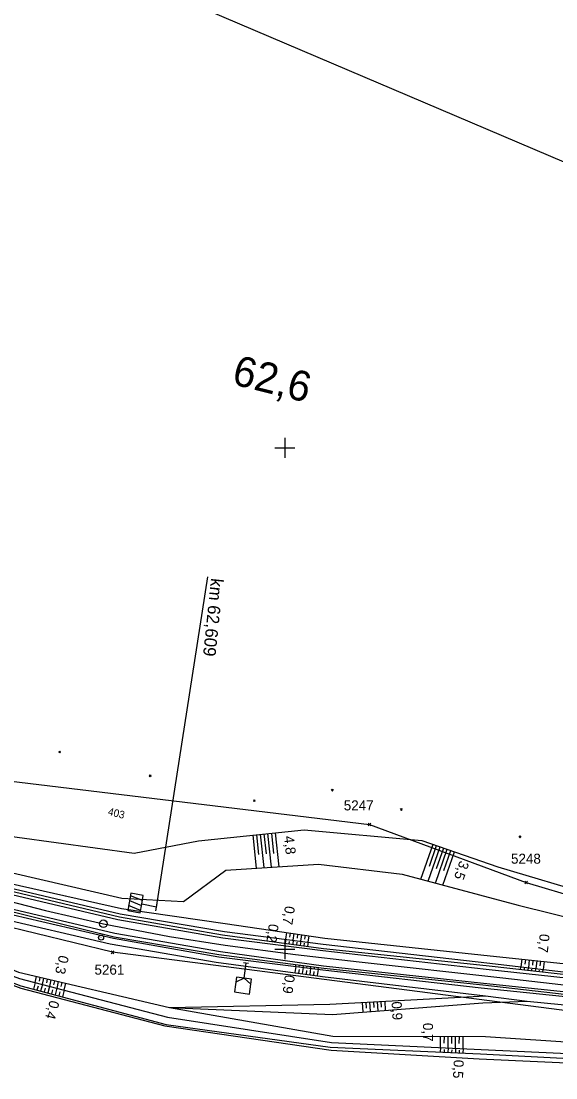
# Model space of a CAD drawing. Extents: x -805636 to -804553, y -1165340 to -1164656.
# Drawn here: x -804952.6 to -804845.9, y -1165125.7 to -1164914.9 of the extents above; entities that cross this region are included whole.
import ezdxf

# ---------------------------------------------------------------- set-up
doc = ezdxf.new("R2010")
doc.units = 0
for name, color, linetype in [('0381KM061-064P - Vrstva 1', 7, 'Continuous'), ('0381KM061-064P - Vrstva 4', 7, 'Continuous'), ('0381KM061-064P - Vrstva 48', 7, 'Continuous'), ('0381KM061-064P - Vrstva 49', 7, 'Continuous'), ('0381KM061-064P - Vrstva 51', 7, 'Continuous'), ('0381KM061-064P - Vrstva 57', 7, 'Continuous'), ('0381KM061-064P - Vrstva 7', 7, 'Continuous'), ('formát', 7, 'Continuous'), ('krizky_1000 - Vrstva 1', 7, 'Continuous'), ('szdc - hran DP', 7, 'Continuous'), ('szdc - szdc_cislo', 7, 'Continuous'), ('szdc - szdc_krizek', 7, 'Continuous')]:
    doc.layers.add(name, color=color, linetype=linetype)

msp = doc.modelspace()

# ---------------------------------------------------------------- linework, layer by layer
at = {"layer": '0381KM061-064P - Vrstva 1'}
for points in [[(-805053.13, -1165050.53), (-805043.64, -1165055.76), (-805030.64, -1165062.45), (-805014.61, -1165069.88), (-804997.39, -1165076.92), (-804978.26, -1165083.66), (-804962.13, -1165088.54), (-804947.73, -1165092.28), (-804936.17, -1165094.91), (-804922.95, -1165097.46), (-804911.85, -1165099.22)], [(-804911.85, -1165099.22), (-804897.85, -1165101.07), (-804885.13, -1165102.52)], [(-804885.13, -1165102.52), (-804856.51, -1165105.73), (-804836.78, -1165107.96), (-804807.43, -1165111.28), (-804800.55, -1165112.05)]]:
    msp.add_lwpolyline(points, dxfattribs=at)
at = {"layer": '0381KM061-064P - Vrstva 4'}
for points in [[(-805080.11, -1165031.8), (-805059.18, -1165044.72), (-805045.31, -1165052.51), (-805029.54, -1165060.96), (-805010.72, -1165069.47), (-804990.45, -1165077.48), (-804974.57, -1165082.73), (-804955.28, -1165088.2), (-804932.96, -1165093.51), (-804912.39, -1165097.1), (-804892.28, -1165099.85)], [(-805080.47, -1165032.5), (-805059.19, -1165045.48), (-805045.86, -1165053.03), (-805029.76, -1165061.31), (-805010.76, -1165070.1), (-804990.66, -1165078.03), (-804974.85, -1165083.28), (-804955.57, -1165088.82), (-804933.31, -1165094.09), (-804912.36, -1165097.73), (-804892.37, -1165100.24)], [(-805082.08, -1165035.58), (-805060.58, -1165048.58), (-805047.98, -1165055.77), (-805031.23, -1165064.28), (-805013.07, -1165072.73), (-804991.62, -1165081.24), (-804976.47, -1165086.37), (-804956.64, -1165091.96), (-804934.05, -1165097.54), (-804913.13, -1165101.06), (-804892.22, -1165103.81)], [(-805082.03, -1165034.98), (-805060.37, -1165047.85), (-805047.54, -1165055.28), (-805031.06, -1165063.92), (-805012.89, -1165072.24), (-804991.69, -1165080.62), (-804976.05, -1165085.82), (-804956.42, -1165091.49), (-804933.87, -1165096.82), (-804912.82, -1165100.43), (-804892.24, -1165103.28)], [(-804892.37, -1165100.24), (-804859.84, -1165103.98), (-804840.8, -1165106.06), (-804819.65, -1165108.38), (-804802.7, -1165110.3), (-804799.92, -1165110.56)], [(-804892.28, -1165099.85), (-804859.81, -1165103.25), (-804840.34, -1165105.46), (-804819.52, -1165107.92), (-804802.69, -1165109.64), (-804799.68, -1165110)], [(-804892.24, -1165103.28), (-804860.33, -1165106.74), (-804841.86, -1165108.69), (-804820.53, -1165111.13), (-804802.92, -1165113.13), (-804801.1, -1165113.34)], [(-804892.22, -1165103.81), (-804860.51, -1165107.09), (-804841.9, -1165109.22), (-804820.58, -1165111.74), (-804803.21, -1165114.08), (-804801.49, -1165114.25)]]:
    msp.add_lwpolyline(points, dxfattribs=at)
at = {"layer": '0381KM061-064P - Vrstva 48'}
for p, q in [((-804905.61, -1165083.83), (-804906.31, -1165077.25)), ((-804905.14, -1165081.14), (-804905.57, -1165077.17)), ((-804904.11, -1165083.73), (-804904.83, -1165077.09)), ((-804903.65, -1165081.01), (-804904.08, -1165077.01)), ((-804902.62, -1165083.64), (-804903.34, -1165076.93)), ((-804902.16, -1165080.89), (-804902.59, -1165076.85)), ((-804901.12, -1165083.54), (-804901.85, -1165076.77)), ((-804872.83, -1165086.04), (-804870.41, -1165079.07)), ((-804871.37, -1165086.42), (-804868.99, -1165079.56)), ((-804871.14, -1165083.47), (-804869.7, -1165079.32)), ((-804869.92, -1165086.81), (-804867.58, -1165080.06)), ((-804869.7, -1165083.89), (-804868.29, -1165079.81)), ((-804868.26, -1165084.32), (-804866.87, -1165080.3)), ((-804868.47, -1165087.2), (-804866.16, -1165080.55)), ((-804899.77, -1165098.02), (-804899.57, -1165096.67)), ((-804898.95, -1165097.58), (-804898.83, -1165096.78)), ((-804898.29, -1165098.2), (-804898.09, -1165096.89)), ((-804897.46, -1165097.78), (-804897.35, -1165097)), ((-804896.8, -1165098.39), (-804896.61, -1165097.11)), ((-804895.98, -1165097.98), (-804895.87, -1165097.22)), ((-804895.31, -1165098.58), (-804895.12, -1165097.33)), ((-804899.78, -1165098.02), (-804899.89, -1165098.81)), ((-804899.08, -1165098.43), (-804899.15, -1165098.91)), ((-804898.29, -1165098.2), (-804898.4, -1165099.01)), ((-804897.59, -1165098.62), (-804897.66, -1165099.12)), ((-804896.8, -1165098.39), (-804896.92, -1165099.22)), ((-804896.11, -1165098.82), (-804896.17, -1165099.32)), ((-804895.32, -1165098.58), (-804895.43, -1165099.42)), ((-804897.81, -1165103.45), (-804897.97, -1165104.67)), ((-804897.8, -1165103.45), (-804897.75, -1165103.08)), ((-804897.04, -1165103.4), (-804897.01, -1165103.18)), ((-804896.32, -1165103.64), (-804896.49, -1165104.86)), ((-804896.31, -1165103.64), (-804896.27, -1165103.28)), ((-804895.55, -1165103.59), (-804895.52, -1165103.38)), ((-804894.83, -1165103.83), (-804894.78, -1165103.48)), ((-804894.06, -1165103.78), (-804894.04, -1165103.57)), ((-804893.34, -1165104.02), (-804893.29, -1165103.67)), ((-804852.96, -1165103.52), (-804853.02, -1165104.02)), ((-804852.82, -1165103.53), (-804852.66, -1165101.96)), ((-804852.01, -1165102.99), (-804851.91, -1165102.04)), ((-804851.33, -1165103.71), (-804851.17, -1165102.11)), ((-804850.52, -1165103.15), (-804850.42, -1165102.19)), ((-804849.84, -1165103.88), (-804849.67, -1165102.27)), ((-804849.03, -1165103.32), (-804848.93, -1165102.35)), ((-804848.35, -1165104.05), (-804848.18, -1165102.43)), ((-804949.77, -1165106.66), (-804949.49, -1165105.44)), ((-804948.93, -1165106.36), (-804948.76, -1165105.61)), ((-804948.32, -1165107.04), (-804948.03, -1165105.78)), ((-804897.13, -1165104.03), (-804897.23, -1165104.77)), ((-804895.64, -1165104.23), (-804895.74, -1165104.97)), ((-804894.83, -1165103.83), (-804895, -1165105.06)), ((-804894.16, -1165104.42), (-804894.26, -1165105.16)), ((-804893.35, -1165104.02), (-804893.51, -1165105.26)), ((-804852.24, -1165103.8), (-804852.27, -1165104.11)), ((-804851.47, -1165103.69), (-804851.53, -1165104.19)), ((-804850.75, -1165103.98), (-804850.78, -1165104.28)), ((-804849.98, -1165103.86), (-804850.04, -1165104.36)), ((-804849.26, -1165104.15), (-804849.29, -1165104.44)), ((-804848.49, -1165104.04), (-804848.55, -1165104.53)), ((-804949.79, -1165106.66), (-804950.13, -1165107.96)), ((-804949.2, -1165107.37), (-804949.41, -1165108.15)), ((-804948.34, -1165107.04), (-804948.69, -1165108.34)), ((-804947.75, -1165107.75), (-804947.96, -1165108.54)), ((-804947.47, -1165106.72), (-804947.29, -1165105.95)), ((-804946.89, -1165107.42), (-804947.24, -1165108.73)), ((-804946.86, -1165107.42), (-804946.56, -1165106.12)), ((-804946.02, -1165107.08), (-804945.83, -1165106.29)), ((-804945.44, -1165107.79), (-804945.79, -1165109.12)), ((-804945.41, -1165107.8), (-804945.1, -1165106.46)), ((-804944.56, -1165107.45), (-804944.37, -1165106.63)), ((-804943.96, -1165108.18), (-804943.64, -1165106.8)), ((-804946.3, -1165108.13), (-804946.51, -1165108.92)), ((-804944.85, -1165108.51), (-804945.06, -1165109.31)), ((-804943.98, -1165108.17), (-804944.34, -1165109.5)), ((-804884.38, -1165112.57), (-804884.48, -1165110.6)), ((-804883.67, -1165111.73), (-804883.73, -1165110.56)), ((-804882.88, -1165112.45), (-804882.99, -1165110.52)), ((-804882.18, -1165111.63), (-804882.24, -1165110.48)), ((-804881.39, -1165112.33), (-804881.49, -1165110.44)), ((-804880.68, -1165111.53), (-804880.74, -1165110.4)), ((-804879.89, -1165112.22), (-804879.99, -1165110.36)), ((-804868.92, -1165119.6), (-804868.91, -1165117.37)), ((-804868.17, -1165118.73), (-804868.16, -1165117.37)), ((-804867.42, -1165119.67), (-804867.41, -1165117.37)), ((-804866.67, -1165118.77), (-804866.66, -1165117.38)), ((-804865.92, -1165119.74), (-804865.91, -1165117.38)), ((-804865.17, -1165118.81), (-804865.16, -1165117.38)), ((-804864.42, -1165119.8), (-804864.41, -1165117.38)), ((-804868.92, -1165119.6), (-804868.96, -1165120.51)), ((-804868.18, -1165120), (-804868.21, -1165120.54)), ((-804867.42, -1165119.67), (-804867.46, -1165120.58)), ((-804866.68, -1165120.06), (-804866.71, -1165120.61)), ((-804865.92, -1165119.74), (-804865.96, -1165120.65)), ((-804865.19, -1165120.13), (-804865.21, -1165120.68)), ((-804864.42, -1165119.8), (-804864.46, -1165120.71))]:
    msp.add_line(p, q, dxfattribs=at)
at = {"layer": '0381KM061-064P - Vrstva 49'}
for p, q in [((-804944.72, -1165060.86), (-804945.08, -1165060.51)), ((-804944.72, -1165060.51), (-804945.08, -1165060.86)), ((-804926.67, -1165065.65), (-804927.02, -1165065.3)), ((-804926.67, -1165065.3), (-804927.02, -1165065.65)), ((-804890.35, -1165068.45), (-804890.7, -1165068.09)), ((-804890.35, -1165068.09), (-804890.7, -1165068.45)), ((-804905.87, -1165070.56), (-804906.22, -1165070.21)), ((-804905.87, -1165070.21), (-804906.22, -1165070.56)), ((-804876.55, -1165072.32), (-804876.9, -1165071.96)), ((-804876.55, -1165071.96), (-804876.9, -1165072.32)), ((-804852.89, -1165077.76), (-804853.25, -1165077.4)), ((-804852.89, -1165077.4), (-804853.25, -1165077.76))]:
    msp.add_line(p, q, dxfattribs=at)
for points in [[(-805085.43, -1165039.91), (-805061.8, -1165053.37), (-805034.45, -1165069.27), (-805016.82, -1165079.3), (-804984.87, -1165094.97), (-804952.63, -1165107.29), (-804923.66, -1165115.02), (-804890.91, -1165119.51), (-804860.93, -1165120.87), (-804821.85, -1165122.9), (-804805.33, -1165123.27)], [(-805084.74, -1165039.06), (-805061.55, -1165052.74), (-805034.17, -1165068.7), (-805016.31, -1165078.58), (-804984.31, -1165094.26), (-804952.92, -1165105.84), (-804923.4, -1165113.55), (-804890.69, -1165118.62), (-804860.79, -1165119.97), (-804821.99, -1165121.8), (-804804.98, -1165122.47)], [(-805060.73, -1165049.17), (-805031.5, -1165064.84), (-805013.36, -1165073.14), (-804991.7, -1165081.91), (-804976.67, -1165086.76), (-804957.06, -1165092.46), (-804934.14, -1165097.81), (-804913.12, -1165101.52), (-804892.37, -1165104.14)], [(-805060.73, -1165049.17), (-805047.98, -1165055.77), (-805031.23, -1165064.28), (-805013.07, -1165072.73), (-804991.62, -1165081.24), (-804976.47, -1165086.37), (-804956.64, -1165091.96), (-804934.05, -1165097.54), (-804913.13, -1165101.06), (-804892.22, -1165103.81), (-804860.51, -1165107.09), (-804841.9, -1165109.22), (-804820.58, -1165111.74), (-804811.31, -1165113.56)], [(-805014.74, -1165060.42), (-805013.72, -1165061.35), (-805008.65, -1165063.79), (-805007.41, -1165061.32), (-805005.07, -1165061.94), (-804999.18, -1165065.52), (-804973.34, -1165074.67), (-804953.36, -1165077.67), (-804930.03, -1165080.86)], [(-805032.39, -1165065.25), (-805013.72, -1165073.73), (-804991.69, -1165082.79), (-804976.92, -1165087.4), (-804957.71, -1165093.59), (-804934.8, -1165098.93), (-804913.68, -1165102.56), (-804892.44, -1165105.41)], [(-805033.41, -1165066.35), (-805014.98, -1165076.25), (-804982.53, -1165092.31), (-804953.12, -1165104.6), (-804922.96, -1165111.59), (-804890.43, -1165117.32), (-804859.92, -1165117.39), (-804821.94, -1165119.94), (-804804.42, -1165121.15)], [(-805010.72, -1165069.47), (-804990.45, -1165077.48), (-804974.57, -1165082.73), (-804955.28, -1165088.2), (-804932.96, -1165093.51), (-804912.39, -1165097.1), (-804892.28, -1165099.85), (-804859.81, -1165103.25), (-804840.34, -1165105.46), (-804819.52, -1165107.92), (-804802.69, -1165109.64), (-804799.68, -1165110)], [(-804995.17, -1165073.22), (-804973.67, -1165080.7), (-804954.98, -1165086.86), (-804932.57, -1165091.85), (-804911.87, -1165094.85)], [(-804994.86, -1165072.51), (-804973.16, -1165079.86), (-804954.29, -1165084.75), (-804932.5, -1165089.79), (-804920.22, -1165090.5), (-804911.77, -1165084.22), (-804893.29, -1165083.05), (-804876.57, -1165085.04), (-804853.44, -1165091.21), (-804839.72, -1165094.63), (-804814.35, -1165098.18)], [(-804930.03, -1165080.86), (-804917.17, -1165078.41), (-804896.14, -1165076.16), (-804872.64, -1165078.3), (-804857.5, -1165083.55), (-804838.27, -1165089.29), (-804812.85, -1165092.56), (-804796.39, -1165094.52), (-804793.24, -1165094.87)], [(-804955.12, -1165087.69), (-804932.8, -1165092.95), (-804911.98, -1165096.48), (-804892.31, -1165098.96)], [(-804911.87, -1165094.85), (-804892.03, -1165097.79)], [(-804892.31, -1165098.96), (-804859.08, -1165102.8), (-804835.93, -1165105.5), (-804818.93, -1165107.36), (-804802.32, -1165108.93), (-804799.37, -1165109.27)], [(-804892.03, -1165097.79), (-804859.05, -1165101.29), (-804840.64, -1165103.22)], [(-804892.44, -1165105.41), (-804859.96, -1165109.29), (-804851.61, -1165110.39), (-804821.13, -1165113.33), (-804811.31, -1165113.56)], [(-804892.37, -1165104.14), (-804860.79, -1165107.69), (-804842.05, -1165109.66), (-804820.85, -1165112.11), (-804811.31, -1165113.56)], [(-804922.96, -1165111.59), (-804890.98, -1165110.95), (-804859.96, -1165109.29)], [(-804922.96, -1165111.59), (-804890.49, -1165113.04), (-804860.47, -1165110.71), (-804851.61, -1165110.39)]]:
    msp.add_lwpolyline(points, dxfattribs=at)
at = {"layer": '0381KM061-064P - Vrstva 51'}
msp.add_lwpolyline([(-805085.93, -1165040.55), (-805062.08, -1165054.12), (-805034.69, -1165069.73), (-805017.21, -1165079.65), (-804985.71, -1165095.39), (-804952.66, -1165107.75), (-804923.93, -1165115.31), (-804890.75, -1165120.1), (-804861.18, -1165121.85), (-804821.92, -1165123.67), (-804805.64, -1165124)], dxfattribs=at)
at = {"layer": '0381KM061-064P - Vrstva 7'}
for p, q in [((-804925.59, -1165091.6), (-804915.32, -1165025.75)), ((-804930.94, -1165090.31), (-804928.58, -1165091.28)), ((-804928.39, -1165090.29), (-804930.75, -1165089.33)), ((-804925.73, -1165092.34), (-804925.45, -1165090.86)), ((-804928.77, -1165092.26), (-804931.13, -1165091.29)), ((-804936.58, -1165097.69), (-804936.68, -1165097.67)), ((-804907.2, -1165102.86), (-804908.19, -1165102.73)), ((-804908.11, -1165105.77), (-804907.69, -1165102.79))]:
    msp.add_line(p, q, dxfattribs=at)
for points in [[(-804925.59, -1165091.6), (-804928.53, -1165091.03), (-804928.2, -1165089.31), (-804930.66, -1165088.84), (-804931.32, -1165092.27), (-804928.86, -1165092.75), (-804928.53, -1165091.03)], [(-804908.11, -1165105.77), (-804909.59, -1165105.56), (-804910, -1165108.53), (-804907.03, -1165108.94), (-804906.62, -1165105.97), (-804908.11, -1165105.77)], [(-804906.76, -1165106.96), (-804908.11, -1165105.77), (-804909.73, -1165106.55)]]:
    msp.add_lwpolyline(points, dxfattribs=at)
for centre, radius in [((-804936.17, -1165094.91), 0.75), ((-804936.63, -1165097.68), 0.5)]:
    msp.add_circle(centre, radius, dxfattribs=at)
at = {"layer": 'formát'}
msp.add_line((-804746.36, -1164984.69), (-804939.6, -1164902.47), dxfattribs=at)
at = {"layer": 'krizky_1000 - Vrstva 1'}
for points in [[(-804900, -1164998), (-804900, -1165002)], [(-804902, -1165000), (-804898, -1165000)], [(-804900, -1165098), (-804900, -1165102)], [(-804902, -1165100), (-804898, -1165100)]]:
    msp.add_lwpolyline(points, dxfattribs=at)
at = {"layer": 'szdc - hran DP'}
for p, q in [((-804991.93, -1165061.99), (-804883.1, -1165075.15)), ((-804883.1, -1165075.15), (-804851.84, -1165086.69)), ((-804851.84, -1165086.69), (-804818.68, -1165096.66)), ((-804934.32, -1165100.62), (-804968.55, -1165092.26)), ((-804802.89, -1165117.55), (-804934.32, -1165100.62))]:
    msp.add_line(p, q, dxfattribs=at)
at = {"layer": 'szdc - szdc_krizek'}
for p, q in [((-804882.83, -1165075.42), (-804883.37, -1165074.89)), ((-804883.37, -1165075.42), (-804882.83, -1165074.89)), ((-804851.58, -1165086.96), (-804852.11, -1165086.43)), ((-804852.11, -1165086.96), (-804851.58, -1165086.43)), ((-804934.06, -1165100.89), (-804934.59, -1165100.35)), ((-804934.59, -1165100.89), (-804934.06, -1165100.35))]:
    msp.add_line(p, q, dxfattribs=at)

# ---------------------------------------------------------------- texts
at = {"layer": '0381KM061-064P - Vrstva 48'}
for s, rotation, p in [('4,8', 276.1274, (-804900.15, -1165077.5)), ('3,5', 250.8741, (-804865.05, -1165082.21)), ('0,7', 261.5641, (-804899.92, -1165091.28)), ('0,2', 262.2041, (-804903.16, -1165094.86)), ('0,7', 264.0185, (-804849.13, -1165096.87)), ('0,3', 256.9445, (-804944.98, -1165101.08)), ('0,9', 262.3554, (-804899.94, -1165105.03)), ('0,4', 255.0624, (-804946.83, -1165110.07)), ('0,9', 273.0779, (-804878.69, -1165110.47)), ('0,7', 269.8704, (-804872.42, -1165114.69)), ('0,5', 267.3952, (-804866.27, -1165122.01))]:
    msp.add_text(s, height=2, rotation=rotation, dxfattribs=at).set_placement(p)
at = {"layer": '0381KM061-064P - Vrstva 57'}
msp.add_text('403', height=1.5, rotation=345.9546, dxfattribs=at).set_placement((-804935.37, -1165073.19))
at = {"layer": '0381KM061-064P - Vrstva 7'}
for s, height, rotation, p in [('62,6', 6, 346.0635, (-804910.76, -1164987.27)), ('km 62,609', 2.5, 264.0663, (-804914.69, -1165025.94))]:
    msp.add_text(s, height=height, rotation=rotation, dxfattribs=at).set_placement(p)
at = {"layer": 'szdc - szdc_cislo'}
for s, p in [('5247', (-804888.22, -1165072.32)), ('5248', (-804854.86, -1165082.95)), ('5261', (-804937.94, -1165105.08))]:
    msp.add_text(s, height=2, dxfattribs=at).set_placement(p)

doc.saveas('drawing.dxf')
